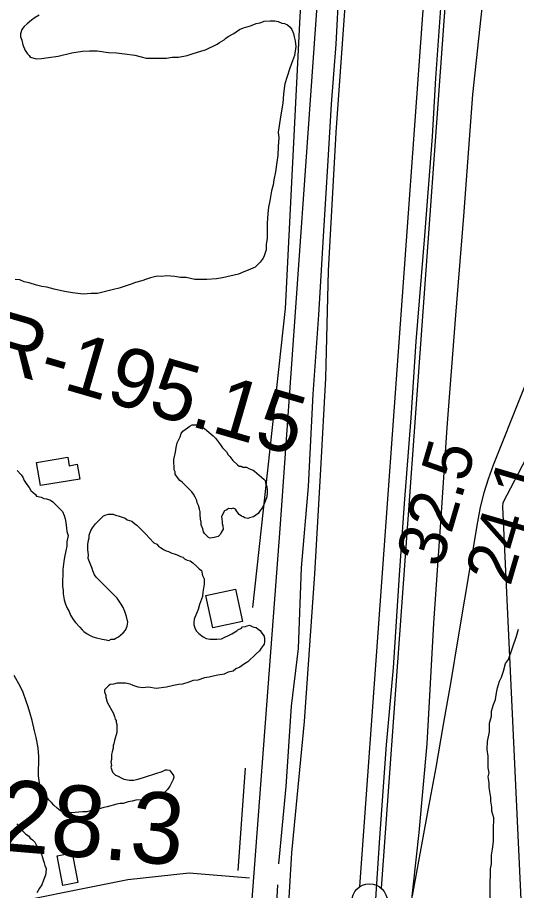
# Model space of a CAD drawing. Extents: x 3324125 to 3362000, y 600753 to 626151.
# Drawn here: x 3332007 to 3332706, y 619010 to 620234 of the extents above; entities that cross this region are included whole.
import ezdxf

# ---------------------------------------------------------------- set-up
doc = ezdxf.new("R2010")
doc.units = 0
for name, color, linetype in [('V-BLDG-OTLN', 7, 'Continuous'), ('V-FLOD-BASE', 7, 'Continuous'), ('V-LEVE-TOET', 7, 'Continuous'), ('V-RIVR-RANG', 7, 'Continuous'), ('V-RIVR-RANG-IDEN', 7, 'Continuous'), ('V-ROAD-CNTR', 7, 'Continuous'), ('V-SITE-VEGE', 7, 'Continuous'), ('V-SURV-IDEN', 7, 'Continuous'), ('V-SURV-LINE', 7, 'Continuous'), ('V-TOPO-MAJR', 7, 'Continuous'), ('V-TOPO-MINR', 7, 'Continuous'), ('V-TOPO-SHOR', 7, 'Continuous')]:
    doc.layers.add(name, color=color, linetype=linetype)

msp = doc.modelspace()

# ---------------------------------------------------------------- linework, layer by layer
at = {"layer": 'V-BLDG-OTLN'}
for points in [[(3332033.4, 619610.1), (3332077.1, 619617.5), (3332079.1, 619605.8), (3332090.3, 619607.7), (3332093.8, 619587.1), (3332038.9, 619577.8)], [(3332270.5, 619423.7), (3332312, 619432.5), (3332321.7, 619387.3), (3332280.2, 619378.5)], [(3332083.2, 619063.1), (3332091.1, 619021.5), (3332070, 619017.5), (3332062.1, 619059)]]:
    msp.add_lwpolyline(points, close=True, dxfattribs=at)
at = {"layer": 'V-FLOD-BASE'}
msp.add_lwpolyline([(3332601.3, 620273.8), (3332592.4, 620148.9), (3332587.7, 620067.3), (3332576.9, 619927.9), (3332564.9, 619779.7), (3332557.8, 619673), (3332548.2, 619552.8), (3332541.2, 619452.5), (3332532.7, 619322.4), (3332523.3, 619214.5), (3332513.7, 619084.4), (3332503.3, 618926.9), (3332491.3, 618785.8), (3332479.3, 618638.2), (3332469.7, 618508.2), (3332468.7, 618442.2), (3332469.4, 618368.7), (3332472.6, 618324.9), (3332485, 618250.7), (3332512, 618101.1)], dxfattribs=at)
at = {"layer": 'V-LEVE-TOET'}
for points in [[(3332544.6, 618179.1), (3332532.3, 618256.8), (3332521.6, 618326.9), (3332514.7, 618422.7), (3332518.2, 618517.2), (3332524.2, 618623.9), (3332535.3, 618731.2), (3332545.3, 618827.5), (3332556.8, 618976.8), (3332569.2, 619091.7), (3332580.5, 619215.9), (3332589.8, 619385.1), (3332600.7, 619540.2), (3332608.5, 619659.2), (3332620.6, 619816.7), (3332632, 619955.5), (3332644.7, 620125.8), (3332661.5, 620282.7)], [(3332465.8, 620256.5), (3332452.4, 620072.8), (3332441.8, 619879.1), (3332437.9, 619728.6), (3332431.2, 619600.3), (3332422.7, 619454.4), (3332408, 619247.3), (3332390.4, 619063.1), (3332380, 618890.4), (3332365.3, 618702), (3332353.2, 618535.8), (3332349, 618436), (3332347.9, 618343.2), (3332355.4, 618248), (3332368.3, 618169.8)]]:
    msp.add_lwpolyline(points, dxfattribs=at)
at = {"layer": 'V-ROAD-CNTR'}
for points in [[(3332435.8, 620389.6), (3332374.7, 619523.7), (3332301.3, 618552.7), (3332296.7, 618455.5), (3332294.2, 618354.6), (3332300.5, 618222.7), (3332312.6, 617992.5), (3332321.2, 617895.8), (3332318.6, 617826.1), (3332311.6, 617761.4), (3332293.4, 617690.8), (3332279.8, 617637.3), (3332250, 617572.9), (3332125.9, 617304.4), (3332097.6, 617233.7), (3332075.6, 617180.9), (3332062.2, 617134.3), (3332055.9, 617103.1), (3332053.1, 617059.6), (3332049, 617007.9), (3332050.3, 616945.8), (3332056, 616867)], [(3331818.3, 618973.3), (3331826.6, 618972.2), (3331927.1, 618976.4), (3331955.7, 618984.5), (3332161.1, 619026), (3332246.9, 619035.2), (3332331.4, 619028.3)]]:
    msp.add_lwpolyline(points, dxfattribs=at)
at = {"layer": 'V-SITE-VEGE'}
for points in [[(3332036.7, 620237.1), (3332031.1, 620233.9), (3332026.3, 620230), (3332019.9, 620225.2), (3332015.9, 620221.3), (3332012.7, 620217.3), (3332011, 620210.9), (3332011, 620207), (3332012.6, 620202.2), (3332014.1, 620195.8), (3332017.2, 620187.8), (3332020.4, 620183), (3332022.8, 620180.6), (3332024.4, 620178.2), (3332033.1, 620175.8), (3332040.3, 620176.5), (3332049.8, 620178), (3332063.4, 620179.5), (3332082.5, 620184.2), (3332097.7, 620186.5), (3332107.3, 620187.2), (3332118.4, 620187.1), (3332134.3, 620184.7), (3332145.5, 620184.6), (3332156.6, 620182.9), (3332170.9, 620181.2), (3332179.7, 620178.8), (3332186.8, 620177.1), (3332215.5, 620177), (3332223.5, 620178.5), (3332232.2, 620178.4), (3332244.2, 620180.8), (3332251.4, 620183.1), (3332265, 620187), (3332269.8, 620188.6), (3332274.5, 620190.9), (3332281.7, 620194.1), (3332286.5, 620196.4), (3332289.7, 620198.8), (3332296.1, 620202.7), (3332298.5, 620205.1), (3332301.7, 620207.5), (3332309.7, 620211.4), (3332312.9, 620213.8), (3332317.7, 620216.9), (3332323.3, 620219.3), (3332332.9, 620222.4), (3332340.9, 620225.5), (3332346.5, 620226.3), (3332352.1, 620228.7), (3332360.8, 620229.4), (3332367.2, 620229.3), (3332372, 620228.5), (3332376.7, 620226.1), (3332380.7, 620225.3), (3332384.7, 620223.7), (3332388.6, 620220.5), (3332391, 620217.2), (3332393.4, 620211.7), (3332394.1, 620206.9), (3332395.7, 620201.3), (3332396.4, 620193.3), (3332394.8, 620180.6), (3332390.7, 620169.5), (3332387.5, 620161.5), (3332381, 620140.8), (3332380.1, 620134.5), (3332379.3, 620126.5), (3332378.4, 620113.8), (3332375.1, 620094.7), (3332373.4, 620082), (3332371.8, 620073.2), (3332372.5, 620065.2), (3332371.6, 620053.3), (3332371.5, 620040.5), (3332369.9, 620031), (3332368.2, 620017.5), (3332365.7, 620006.3), (3332364.9, 619999.2), (3332362.5, 619991.2), (3332360, 619976.9), (3332358.3, 619968.1), (3332357.5, 619959.4), (3332356.6, 619945.9)], [(3332356.6, 619945.9), (3332356.5, 619924.3), (3332354.8, 619916.4), (3332354.8, 619908.4), (3332353.1, 619902.9), (3332352.3, 619899.7), (3332350.7, 619896.5), (3332346.7, 619891), (3332339.5, 619883.8), (3332329.9, 619879.9), (3332323.5, 619877.6), (3332316.3, 619874.4), (3332294, 619869), (3332285.2, 619867.5), (3332271.7, 619866.8), (3332254.9, 619866.9), (3332243, 619869.3), (3332235, 619869.4), (3332227.1, 619871), (3332215.9, 619871.9), (3332208.8, 619871.1), (3332202.4, 619871.2), (3332192.8, 619868.9), (3332187.2, 619867.3), (3332180.8, 619864.9), (3332172.1, 619862.6), (3332165.7, 619860.3), (3332148.9, 619854.8), (3332140.9, 619852.5), (3332118.6, 619847), (3332109.8, 619847.1), (3332098.7, 619846.4), (3332083.6, 619848.1), (3332072.4, 619849.7), (3332058.1, 619853), (3332047.8, 619856.2), (3332040.6, 619857.1), (3332033.4, 619858.7), (3332023.1, 619862), (3332016, 619863.6), (3332009.6, 619866.1), (3332003.2, 619866.9)], [(3332006.3, 619599.2), (3332011.8, 619592.8), (3332014.2, 619589.6), (3332015.7, 619584.8), (3332019.7, 619579.2), (3332022.8, 619575.2), (3332025.2, 619571.2), (3332028.4, 619568), (3332031.6, 619565.6), (3332033.1, 619563.2), (3332039.5, 619561.6), (3332043.5, 619560), (3332047.4, 619559.1), (3332053, 619557.5), (3332056.2, 619555.1), (3332069.6, 619541.5), (3332072, 619535.9), (3332073.5, 619531.1), (3332074.3, 619526.3), (3332075.1, 619518.3), (3332075.8, 619513.6), (3332077.4, 619508), (3332075.7, 619499.2), (3332075.7, 619492.9), (3332074.1, 619486.5), (3332072.4, 619477.7), (3332071.6, 619471.4), (3332069.9, 619460.2), (3332069.8, 619437.1), (3332070.5, 619430.8), (3332070.5, 619426), (3332072, 619418), (3332073.6, 619411.6), (3332076.7, 619405.2), (3332079.1, 619401.2), (3332080.6, 619396.4), (3332084.6, 619390), (3332087.7, 619386), (3332094.1, 619379.6), (3332097.2, 619375.6), (3332099.6, 619373.2), (3332104.4, 619370), (3332108.3, 619367.6), (3332112.3, 619366), (3332117.1, 619364.3), (3332125, 619362.7), (3332130.6, 619361.9), (3332134.6, 619361), (3332137.8, 619362.6), (3332141.8, 619362.6), (3332144.2, 619364.2), (3332148.1, 619365.7), (3332151.4, 619368.9), (3332154.6, 619371.3), (3332157.8, 619375.2), (3332159.4, 619378.4), (3332160.2, 619380.8), (3332161, 619386.4), (3332159.5, 619394.3), (3332157.1, 619401.5), (3332154.8, 619407.1), (3332151.6, 619411.9), (3332146.1, 619419.9), (3332116.8, 619449.6), (3332114.5, 619452.8), (3332112.1, 619458.4), (3332111.3, 619461.6), (3332107.4, 619471.1), (3332105.8, 619475.9), (3332105.9, 619480.7)], [(3332105.9, 619480.7), (3332105.1, 619487.9), (3332105.2, 619495.1), (3332106, 619501.4), (3332106.8, 619504.6), (3332106.9, 619508.6), (3332109.3, 619514.9), (3332111.7, 619518.9), (3332115.7, 619524.5), (3332126.9, 619535.5), (3332130.9, 619537.1), (3332134.1, 619537.9), (3332140.5, 619537.8), (3332143.7, 619536.2), (3332147.6, 619535.4), (3332153.2, 619533.8), (3332157.2, 619532.2), (3332160.4, 619529.7), (3332166.7, 619528.1), (3332170.7, 619524.9), (3332173.9, 619522.5), (3332186.5, 619509.7), (3332191.3, 619504.1), (3332197.6, 619497.6), (3332201.6, 619496), (3332203.9, 619492.8), (3332207.1, 619491.2), (3332211.9, 619488), (3332215, 619486.4), (3332218.2, 619485.6), (3332223, 619483.1), (3332226.2, 619482.3), (3332230.1, 619480.7), (3332234.9, 619478.3), (3332238.1, 619477.5), (3332240.5, 619475.1), (3332244.4, 619473.4), (3332248.4, 619472.6), (3332252.4, 619469.4), (3332257.9, 619464.6), (3332261.1, 619461.4), (3332264.2, 619459), (3332265.8, 619451.8), (3332268.1, 619447), (3332268.1, 619439.8), (3332266.4, 619428.7), (3332265.6, 619422.3), (3332261.5, 619411.2), (3332259.9, 619404), (3332257.5, 619398.5), (3332254.2, 619390.5), (3332253.4, 619385.8), (3332253.4, 619382.6), (3332255.7, 619377), (3332257.3, 619373.8), (3332260.5, 619370.6), (3332266.8, 619365.8), (3332270.8, 619363.4), (3332276.4, 619362.5), (3332285.9, 619362.5), (3332292.3, 619363.2), (3332306.7, 619370.3), (3332313.9, 619374.2), (3332315.5, 619375.8), (3332320.3, 619378.2), (3332321.9, 619379.8), (3332325.9, 619380.5), (3332328.3, 619381.3), (3332331.5, 619382.1), (3332335.4, 619380.5), (3332337.8, 619379.6), (3332341, 619378.8), (3332344.2, 619376.4), (3332346.5, 619374.8), (3332348.1, 619372.4), (3332350.5, 619369.2), (3332352.1, 619366.8), (3332352.8, 619362.8), (3332352.8, 619359.6), (3332352, 619355.7), (3332348, 619350.1), (3332345.6, 619346.1), (3332340.8, 619342.2), (3332329.5, 619331.1), (3332324.7, 619328), (3332318.3, 619323.2), (3332312.7, 619320.9), (3332308.7, 619317.7), (3332301.6, 619316.2), (3332296, 619313.8), (3332287.2, 619312.3), (3332280.8, 619310.7), (3332275.2, 619309.2), (3332268.8, 619308.4), (3332259.3, 619305.3), (3332252.9, 619304.5), (3332246.5, 619302.2), (3332237.7, 619299.8), (3332232.1, 619299.1), (3332225, 619297.5), (3332215.4, 619295.2)], [(3332668.9, 618995.5), (3332669, 619013.3), (3332669.2, 619040.8), (3332670.6, 619047.6), (3332670.7, 619060), (3332672.1, 619068.2), (3332673.6, 619079.1), (3332673.7, 619095.6), (3332673.8, 619112.1), (3332671.1, 619121.7), (3332671.1, 619127.2), (3332669.8, 619135.4), (3332669.8, 619140.9), (3332668.5, 619149.1), (3332667.2, 619154.6), (3332667.2, 619161.5), (3332665.9, 619169.7), (3332667.3, 619175.2), (3332666, 619182.1), (3332666.1, 619198.5), (3332664.8, 619208.1), (3332664.9, 619219.1), (3332667.7, 619232.8), (3332667.7, 619238.3), (3332667.8, 619245.1), (3332670.6, 619254.7), (3332670.6, 619261.6), (3332673.4, 619271.2), (3332676.2, 619278), (3332677.7, 619287.6), (3332679.1, 619294.5), (3332681.9, 619304), (3332684.7, 619309.5), (3332687.4, 619317.7), (3332690.3, 619328.7), (3332694.4, 619334.1), (3332705.6, 619367), (3332708.4, 619376.6)], [(3332215.4, 619295.2), (3332201, 619293.7), (3332189.9, 619295.4), (3332181.9, 619294.6), (3332175.6, 619295.5), (3332168.4, 619297.9), (3332164.4, 619299.5), (3332158.1, 619301.2), (3332146.1, 619301.2), (3332141.3, 619299.7), (3332136.6, 619298.9), (3332134.2, 619297.3), (3332128.6, 619291.8), (3332128.5, 619288.6), (3332130.1, 619283.8), (3332130.1, 619281.4), (3332132.4, 619274.2), (3332141.1, 619258.3), (3332142.6, 619254.3), (3332143.4, 619250.3), (3332145, 619248.7), (3332145, 619246.3), (3332145.8, 619243.1), (3332145.7, 619231.9), (3332144.9, 619228.8), (3332143.2, 619224), (3332142.4, 619220.8), (3332141.6, 619216), (3332140.8, 619213.6), (3332140.8, 619209.7), (3332139.1, 619204.9), (3332138.3, 619200.9), (3332138.3, 619193.8), (3332137.5, 619190.6), (3332138.2, 619185.8), (3332137.4, 619183.4), (3332139.8, 619176.2), (3332143.7, 619172.2), (3332147.7, 619170.6), (3332151.6, 619168.2), (3332155.6, 619166.6), (3332163.6, 619164.9), (3332169.2, 619164.9), (3332175.5, 619166.4), (3332185.9, 619169.5), (3332200.3, 619174.2), (3332209.1, 619177.4), (3332213.8, 619179.7), (3332216.2, 619179.7), (3332219.4, 619178.9), (3332221, 619177.3), (3332222.6, 619174.9), (3332225, 619171.7), (3332225.7, 619169.3), (3332224.9, 619166.1), (3332220.1, 619156.6), (3332216.9, 619151.8), (3332211.2, 619146.3), (3332205.7, 619143.9), (3332199.3, 619142.4), (3332191.3, 619140), (3332185.7, 619138.5), (3332180.1, 619137.7), (3332172.2, 619137), (3332167.4, 619135.4), (3332161.8, 619134.7), (3332154.6, 619132.3), (3332150.6, 619132.3), (3332145.8, 619131.6), (3332132.3, 619127.7), (3332127.5, 619126.9), (3332119.5, 619124.6), (3332116.3, 619123.8), (3332111.5, 619123), (3332103.6, 619120.7), (3332098, 619120.7), (3332092.4, 619120), (3332082, 619119.2), (3332077.3, 619120.1), (3332073.3, 619120.1), (3332067.7, 619121.7), (3332064.5, 619124.1), (3332062.2, 619125.7), (3332057.4, 619129.8), (3332054.3, 619133.8), (3332051.1, 619137), (3332045.6, 619143.4), (3332041.6, 619149), (3332037.7, 619157.8), (3332036.2, 619171.3), (3332036.3, 619198.4), (3332035.6, 619210.3), (3332032.5, 619224.7), (3332030.2, 619234.3), (3332027.1, 619248.6), (3332024, 619259.8), (3332021.7, 619267.8), (3332018.5, 619275.8), (3332014.6, 619287.7), (3332010.7, 619295.7), (3332002, 619311.7)], [(3332005.5, 619103.8), (3332007.1, 619102.2), (3332013.4, 619094.2), (3332018.1, 619089.4), (3332022.1, 619087), (3332024.5, 619083.8), (3332027.6, 619081.4), (3332030.8, 619078.2), (3332036.3, 619067), (3332038.7, 619063.8), (3332040.2, 619061.4), (3332041.8, 619056.6), (3332042.6, 619053.4), (3332044.1, 619049.4), (3332044.9, 619045.4), (3332046.5, 619041.4), (3332046.4, 619035), (3332045.6, 619031.9), (3332043.2, 619024.7), (3332040.8, 619018.3), (3332037.5, 619013.6), (3332033.5, 619007.2)]]:
    msp.add_lwpolyline(points, dxfattribs=at)
msp.add_lwpolyline([(3332351.9, 619586.7), (3332353.5, 619585.1), (3332354.2, 619581.9), (3332355.8, 619576.3), (3332356.6, 619572.3), (3332356.6, 619568.3), (3332355.7, 619561.9), (3332354.1, 619557.2), (3332352.5, 619553.2), (3332349.2, 619546.8), (3332346.8, 619542.9), (3332343.6, 619538.9), (3332337.2, 619534.2), (3332331.6, 619532.6), (3332329.2, 619531.8), (3332325.3, 619532.7), (3332322.9, 619534.3), (3332320.5, 619535.1), (3332317.3, 619537.5), (3332315.7, 619539.1), (3332313.4, 619542.3), (3332311.8, 619544.7), (3332308.6, 619546.3), (3332306.2, 619545.5), (3332302.2, 619545.6), (3332299.8, 619544), (3332296.6, 619542.4), (3332292.6, 619534.5), (3332293.4, 619527.3), (3332293.3, 619524.9), (3332294.1, 619521.7), (3332294.9, 619516.9), (3332291.7, 619512.2), (3332290.9, 619509.8), (3332287.7, 619506.6), (3332282.1, 619505.1), (3332276.5, 619504.3), (3332274.1, 619505.1), (3332268.6, 619510.7), (3332267, 619513.1), (3332266.2, 619517.1), (3332263.9, 619522.7), (3332263.9, 619526.7), (3332263.1, 619530.7), (3332262.4, 619537.1), (3332262.4, 619541), (3332261.6, 619545), (3332260.1, 619549.8), (3332258.5, 619553.8), (3332257.7, 619557), (3332255.4, 619561.8), (3332253, 619565.8), (3332250.6, 619569), (3332237.2, 619582.6), (3332234, 619585), (3332230.8, 619589), (3332227.7, 619593.8), (3332227.7, 619597), (3332226.1, 619600.2), (3332226.2, 619605), (3332225.4, 619609), (3332225.4, 619614.6), (3332227.9, 619624.9), (3332228.7, 619631.3), (3332230.4, 619637.6), (3332234.4, 619646.4), (3332236, 619651.1), (3332238.4, 619654.3), (3332248, 619661.4), (3332251.2, 619663), (3332258.4, 619662.9), (3332261.6, 619662.1), (3332266.3, 619659.7), (3332268.7, 619658.1), (3332271.9, 619654.9), (3332280.6, 619647.6), (3332283.8, 619644.4), (3332290.9, 619634.8), (3332294, 619630.8), (3332299.6, 619625.2), (3332301.9, 619621.2), (3332304.3, 619618.8), (3332308.3, 619613.2), (3332314.6, 619606.8), (3332317, 619605.2), (3332320.1, 619605.2), (3332322.5, 619603.6), (3332327.3, 619603.5), (3332330.5, 619601.9), (3332332.9, 619601.1), (3332336.8, 619599.5), (3332338.4, 619597.9)], close=True, dxfattribs=at)
at = {"layer": 'V-SURV-LINE'}
for points in [[(3332486.2, 619015.8), (3332657, 621382)], [(3332687, 621379.8), (3332516.2, 619013.7)]]:
    msp.add_lwpolyline(points, dxfattribs=at)
msp.add_circle((3332499.8, 618994.8), 25, dxfattribs=at)
at = {"layer": 'V-TOPO-MAJR'}
msp.add_lwpolyline([(3333375.7, 620872.5), (3332686.5, 619553.9), (3332686, 619548.3), (3332738.3, 618427.5), (3332736.6, 618393.3), (3332728.3, 618196.5), (3332723.1, 618063.9), (3332718.3, 617931.3), (3332714.4, 617798.6), (3332710.9, 617666), (3332701.6, 617266), (3332701.4, 617252.2), (3332701.5, 617238.3), (3332702, 617224.4), (3332702.8, 617210.5), (3332718.4, 616974.5), (3332723, 616910.5)], dxfattribs=at)
at = {"layer": 'V-TOPO-MINR'}
msp.add_lwpolyline([(3332833.8, 620009.2), (3332673.1, 619606.4), (3332666.1, 619587.1), (3332659.9, 619567.5), (3332655, 619547.5), (3332651, 619527.3), (3332623.7, 619363.3), (3332613.6, 619303.2), (3332603.2, 619243), (3332592.5, 619182.9), (3332581.6, 619122.9), (3332559.4, 619002.9)], dxfattribs=at)
at = {"layer": 'V-TOPO-SHOR'}
msp.add_line((3332325.4, 619181.8), (3332315.2, 619038.6), dxfattribs=at)
for points in [[(3332372.9, 619048), (3332382.8, 619156.3), (3332390.3, 619268.6), (3332400.4, 619349.7), (3332404.7, 619462.4), (3332414.2, 619576.7), (3332420.6, 619706.1), (3332428.9, 619817.1), (3332435.2, 619927), (3332441.8, 620033.7), (3332446.7, 620112.5), (3332453.2, 620196.5), (3332457.3, 620277.3), (3332465.2, 620376.5), (3332468.5, 620469.2), (3332476.4, 620571.9), (3332484.6, 620676.6), (3332492.1, 620780.1), (3332504.8, 620912)], [(3331803.8, 620470.4), (3332397, 620511.3), (3332412.3, 620496), (3332417.5, 620470.4), (3332402.1, 620235.2), (3332381.7, 619826.1), (3332335.6, 619406.8)], [(3332361.2, 617877.9), (3332351, 617985.2), (3332345.9, 618082.4), (3332330.5, 618338.1), (3332335.6, 618563.1), (3332356.1, 618736.9), (3332371.4, 619018.2)]]:
    msp.add_lwpolyline(points, dxfattribs=at)

# ---------------------------------------------------------------- texts
at = {"layer": 'V-RIVR-RANG'}
for s, p in [('32.5', (3332600.2, 619461.1)), ('24.1', (3332696.9, 619435.5))]:
    msp.add_text(s, height=67, rotation=73.6783, dxfattribs=at).set_placement(p)
at = {"layer": 'V-RIVR-RANG-IDEN'}
msp.add_text('R-195.15', height=83, rotation=343.8188, dxfattribs=at).set_placement((3331956.2, 619746.4))
at = {"layer": 'V-SURV-IDEN'}
msp.add_text('5179+28.3', height=100, rotation=355.1811, dxfattribs=at).set_placement((3331602.2, 619098.6))

doc.saveas('drawing.dxf')
